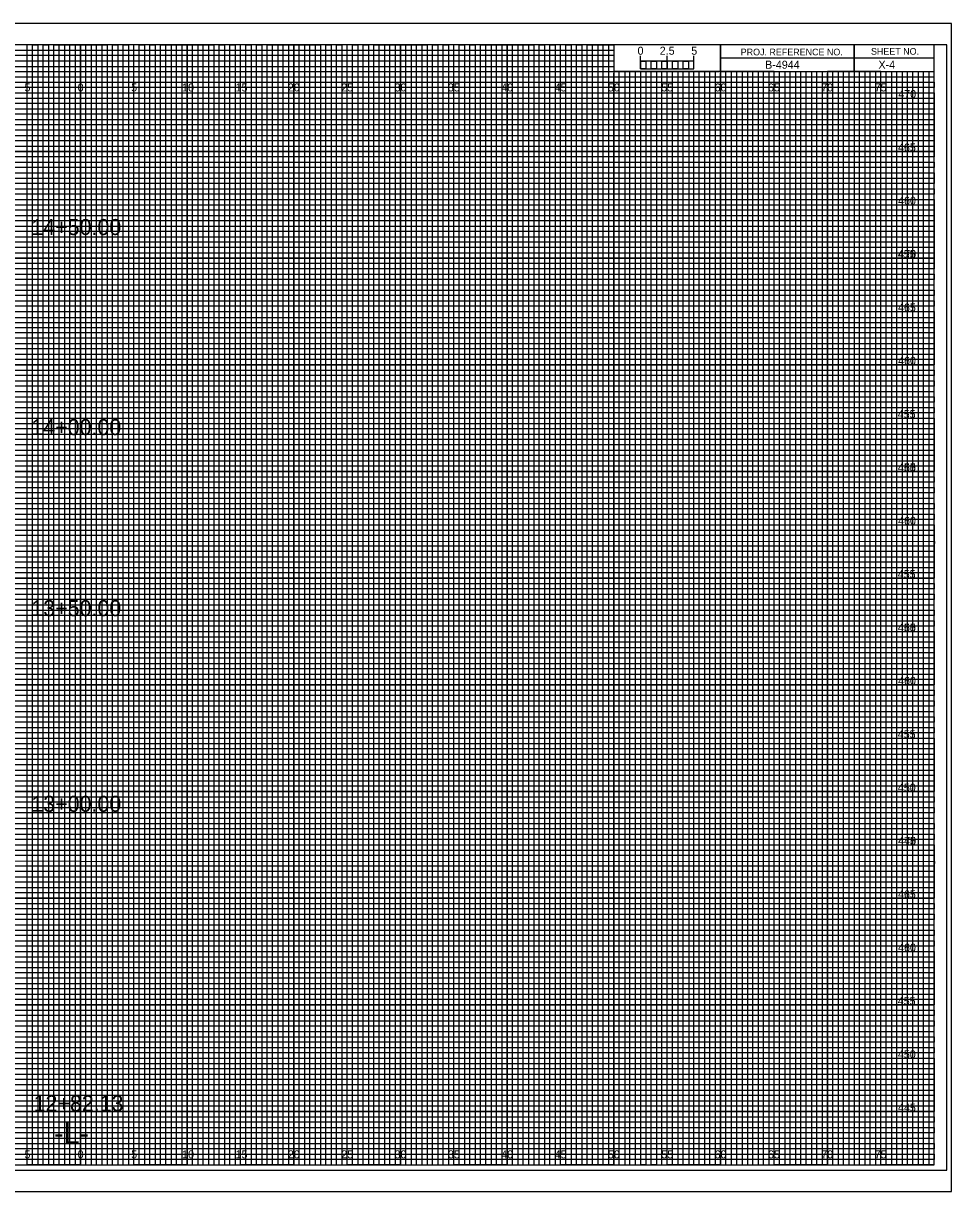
# Model space of a CAD drawing. Extents: x -7 to 162, y 328 to 437.
# Drawn here: x 74.6 to 161.7, y 327.5 to 437 of the extents above; entities that cross this region are included whole.
import ezdxf

# ---------------------------------------------------------------- set-up
doc = ezdxf.new("R2010")
doc.units = 0
for name, color, linetype in [('Prop XS Alignment Label', 7, 'Continuous'), ('Prop XS Bar Scale Labels', 7, 'Continuous'), ('Prop XS Elevation Labels', 7, 'Continuous'), ('Prop XS Offset Labels', 7, 'Continuous'), ('Prop XS Project Number', 7, 'Continuous'), ('Prop XS Sheet Number', 7, 'Continuous'), ('Prop XS Station Labels', 7, 'Continuous'), ('Sheet Cross Section CELL', 7, 'Continuous'), ('Sheet Cross Section Grid Major CELL', 7, 'Continuous'), ('Sheet Cross Section Grid Middle CELL', 7, 'Continuous'), ('Sheet Cross Section Grid Minor 1 CELL', 7, 'Continuous'), ('Sheet Cross Section Grid Minor 2 CELL', 7, 'Continuous'), ('Sheet Cross Section Scale CELL', 7, 'Continuous'), ('Sheet Cutting Line CELL', 7, 'Continuous'), ('Sheet DOT Grid CELL', 7, 'Continuous'), ('Sheet Plot Border Inside CELL', 7, 'Continuous'), ('Sheet Plot Border Outside CELL', 7, 'Continuous')]:
    doc.layers.add(name, color=color, linetype=linetype)

msp = doc.modelspace()

# ---------------------------------------------------------------- linework, layer by layer
at = {"layer": 'Sheet Cross Section CELL'}
for p, q in [((152.5, 435), (152.5, 432.5)), ((152.5, 432.5), (152.5, 435)), ((160, 433.75), (140, 433.75)), ((140, 433.75), (140, 432.5)), ((140, 432.5), (160, 432.5))]:
    msp.add_line(p, q, dxfattribs=at)
for points in [[(160, 435), (0, 435), (0, 330), (160, 330)], [(140, 435), (130, 435), (130, 432.51), (140, 432.51)], [(160, 435), (140, 435), (140, 432.5), (160, 432.5)]]:
    msp.add_lwpolyline(points, close=True, dxfattribs=at)
at = {"layer": 'Sheet Cross Section Grid Major CELL'}
for p, q in [((75, 435), (70, 435)), ((75, 330), (75, 435)), ((85, 435), (80, 435)), ((80, 435), (80, 330)), ((85, 330), (85, 435)), ((95, 435), (90, 435)), ((90, 435), (90, 330)), ((95, 330), (95, 435)), ((105, 435), (100, 435)), ((100, 435), (100, 330)), ((105, 330), (105, 435)), ((115, 435), (110, 435)), ((110, 435), (110, 330)), ((115, 330), (115, 435)), ((125, 435), (120, 435)), ((120, 435), (120, 330)), ((125, 330), (125, 435)), ((130, 435), (130, 330)), ((135, 330), (135, 432.5)), ((145, 432.5), (140, 432.5)), ((140, 432.5), (140, 330)), ((145, 330), (145, 432.5)), ((155, 432.5), (150, 432.5)), ((150, 432.5), (150, 330)), ((155, 330), (155, 432.5)), ((80, 330), (75, 330)), ((90, 330), (85, 330)), ((100, 330), (95, 330)), ((110, 330), (105, 330)), ((120, 330), (115, 330)), ((130, 330), (125, 330)), ((140, 330), (135, 330)), ((150, 330), (145, 330)), ((160, 330), (155, 330)), ((160, 330), (160, 330))]:
    msp.add_line(p, q, dxfattribs=at)
for points in [[(0, 430), (160, 430), (160, 425), (0, 425)], [(0, 420), (160, 420), (160, 415), (0, 415)], [(0, 410), (160, 410), (160, 405), (0, 405)], [(0, 400), (160, 400), (160, 395), (0, 395)], [(0, 390), (160, 390), (160, 385), (0, 385)], [(0, 380), (160, 380), (160, 375), (0, 375)], [(0, 370), (160, 370), (160, 365), (0, 365)], [(0, 360), (160, 360), (160, 355), (0, 355)], [(0, 350), (160, 350), (160, 345), (0, 345)], [(0, 340), (160, 340), (160, 335), (0, 335)]]:
    msp.add_lwpolyline(points, dxfattribs=at)
at = {"layer": 'Sheet Cross Section Grid Middle CELL'}
for points in [[(72.5, 330), (77.5, 330), (77.5, 435), (82.5, 435), (82.5, 330), (87.5, 330), (87.5, 435), (92.5, 435), (92.5, 330), (97.5, 330), (97.5, 435), (102.5, 435), (102.5, 330), (107.5, 330), (107.5, 435), (112.5, 435), (112.5, 330), (117.5, 330), (117.5, 435), (122.5, 435), (122.5, 330), (127.5, 330), (127.5, 435), (129.97, 435), (130, 435), (130, 432.5), (132.5, 432.5), (132.5, 330), (137.5, 330), (137.5, 432.5), (142.5, 432.5), (142.5, 330), (147.5, 330), (147.5, 432.5), (152.5, 432.5), (152.5, 330), (157.5, 330), (157.5, 432.5)], [(0, 432.5), (137.5, 432.5)], [(0, 422.5), (160, 422.5), (160, 427.5), (0, 427.5)], [(0, 412.5), (160, 412.5), (160, 417.5), (0, 417.5)], [(0, 402.5), (160, 402.5), (160, 407.5), (0, 407.5)], [(0, 392.5), (160, 392.5), (160, 397.5), (0, 397.5)], [(0, 382.5), (160, 382.5), (160, 387.5), (0, 387.5)], [(0, 372.5), (160, 372.5), (160, 377.5), (0, 377.5)], [(0, 362.5), (160, 362.5), (160, 367.5), (0, 367.5)], [(0, 352.5), (160, 352.5), (160, 357.5), (0, 357.5)], [(0, 342.5), (160, 342.5), (160, 347.5), (0, 347.5)], [(0, 332.5), (160, 332.5), (160, 337.5), (0, 337.5)]]:
    msp.add_lwpolyline(points, dxfattribs=at)
at = {"layer": 'Sheet Cross Section Grid Minor 1 CELL'}
for p, q in [((0, 434.5), (130, 434.5)), ((130, 433.99), (0, 433.99)), ((130, 434.5), (130, 433.99)), ((0, 433.5), (130, 433.5)), ((130, 432.94), (0, 432.94)), ((130, 433.5), (130, 432.94)), ((0, 432), (160, 432))]:
    msp.add_line(p, q, dxfattribs=at)
for points in [[(0, 431.5), (135, 431.5), (160, 431.5), (160, 431), (0, 431)], [(0, 430.5), (160, 430.5), (160, 429.5), (0, 429.5)], [(0, 429), (160, 429), (160, 428.5), (0, 428.49)], [(0, 428), (160, 428), (160, 427), (0, 427)], [(0, 426.5), (160, 426.5), (160, 426), (0, 426)], [(0, 425.5), (160, 425.5), (160, 424.5), (0, 424.5)], [(0, 424), (160, 424), (160, 423.5), (0, 423.5)], [(0, 423), (160, 423), (160, 422), (0, 422)], [(0, 421.5), (160, 421.5), (160, 421), (0, 421)], [(0, 420.5), (160, 420.5), (160, 419.5), (0, 419.5)], [(0, 419), (160, 419), (160, 418.5), (0, 418.5)], [(0, 418), (160, 418), (160, 416.98), (160, 416.5), (160, 416), (0, 416)], [(0, 417), (160, 417), (160, 416.5), (0, 416.5)], [(0, 415.5), (160, 415.5), (160, 414.5), (0, 414.51)], [(0, 414.51), (160, 414.5), (160, 414), (0, 414)], [(0, 413.5), (160, 413.5), (160, 413), (0, 413)], [(0, 412), (160, 412), (160, 411.5), (0, 411.5)], [(0, 411), (160, 411), (160, 410.5), (0, 410.5)], [(-0.04, 409.44), (160, 409.44), (160, 408.94), (-0.04, 408.94)], [(0, 408.5), (160, 408.5), (160, 408), (0, 408)], [(0, 407), (160, 407), (160, 406.5), (0, 406.5)], [(0, 406), (160, 406), (160, 405.5), (0, 405.5)], [(0, 404.5), (160, 404.5), (160, 404), (0, 404)], [(0, 403.5), (160, 403.5), (160, 403), (0, 403)], [(0, 402), (160, 402), (160, 401.5), (0, 401.5)], [(0, 401), (160, 401), (160, 400.5), (0, 400.5)], [(0, 399.5), (160, 399.5), (160, 398.99), (0, 399)], [(0, 398.5), (160, 398.5), (160, 398), (0, 398)], [(0, 397), (160, 397), (160, 396.5), (0, 396.5)], [(0, 396), (160, 396), (160, 395.5), (0, 395.5)], [(0, 394.5), (160, 394.5), (160, 394), (0, 394)], [(0, 393.5), (160, 393.5), (160, 393), (0, 393)], [(0, 392), (160, 392), (160, 391.5), (0, 391.5)], [(0, 391), (160, 391), (160, 390.5), (0, 390.5)], [(0, 389.5), (160, 389.5), (160, 389), (0, 389)], [(0, 388.5), (160.03, 388.45), (160, 388), (0, 388)], [(0, 387), (160, 387), (160, 386.5), (0, 386.5)], [(0, 386), (160, 386), (160, 385.5), (0, 385.5)], [(0, 384.5), (160, 384.5), (160, 384), (0, 384)], [(0, 383.5), (160, 383.5), (160, 383), (0, 383)], [(0, 382), (160, 382), (160, 381.5), (0, 381.5)], [(0, 381), (160, 381), (160, 380.5), (0, 380.5)], [(0, 379.5), (160, 379.5), (160, 379), (0, 379)], [(0, 378.5), (160, 378.5), (160, 378), (0, 378)], [(0, 377), (160, 377), (160, 376.5), (0, 376.5)], [(0, 376), (160, 376), (160, 375.5), (0, 375.5)], [(0, 374.5), (160, 374.5), (160, 374), (0, 374)], [(0, 373.5), (160, 373.5), (160, 373), (0, 373)], [(0, 372), (160, 372), (160, 371.5), (0, 371.5)], [(0, 371), (160, 371), (160, 370.5), (0, 370.5)], [(0, 369.5), (160, 369.5), (160, 368.99), (0, 369)], [(0, 368.5), (160, 368.5), (160, 368), (0, 368)], [(0, 367), (160, 367), (160, 366.5), (0, 366.5)], [(0, 366), (160, 366), (160, 365.5), (0, 365.5)], [(0, 364.5), (160, 364.5), (160, 364), (0, 364)], [(0, 363.5), (160, 363.5), (160, 363), (0, 363)], [(0, 362), (160, 362), (160, 361.5), (0, 361.5)], [(0, 361), (160, 361), (160, 360.5), (0, 360.5)], [(0, 359.5), (160, 359.5), (160, 359), (0, 359)], [(0, 358.5), (160.03, 358.45), (160, 358), (0, 358)], [(0, 357), (160, 357), (160, 356.5), (0, 356.5)], [(0, 356), (160, 356), (160, 355.5), (0, 355.5)], [(0, 354.5), (160, 354.5), (160, 354), (0, 354)], [(0, 353.5), (160, 353.5), (160, 353), (0, 353)], [(0, 352), (160, 352), (160, 351.5), (0, 351.5)], [(0, 351), (160, 351), (160, 350.5), (0, 350.5)], [(0, 349.5), (160, 349.5), (160, 349), (0, 349)], [(0, 348.5), (160, 348.5), (160, 348), (0, 348)], [(0, 347), (160, 347), (160, 346.5), (0, 346.5)], [(0, 346), (160, 346), (160, 345.5), (0, 345.5)], [(0, 344.5), (160, 344.5), (160, 344), (0, 344)], [(0, 343.5), (160, 343.5), (160, 343), (0, 343)], [(0, 342), (160, 342), (160, 341.5), (0, 341.5)], [(0, 341), (160, 341), (160, 340.5), (0, 340.5)], [(0, 339.5), (160, 339.5), (160, 339), (0, 339)], [(0, 338.5), (160, 338.5), (160, 338), (0, 338)], [(0, 337), (160, 337), (160, 336.5), (0, 336.5)], [(0, 336), (160, 336), (160, 335.5), (0, 335.5)], [(0, 334.5), (160, 334.5), (160, 334), (0, 334)], [(0, 333.5), (160, 333.5), (160, 333), (0, 333)], [(0, 332), (160, 332), (160, 331.5), (0, 331.5)], [(0, 331), (160, 331), (160, 330.5), (0, 330.5)]]:
    msp.add_lwpolyline(points, dxfattribs=at)
at = {"layer": 'Sheet Cross Section Grid Minor 2 CELL'}
for p, q in [((133.5, 432.5), (133, 432.5)), ((133, 432.5), (133, 330)), ((133.5, 330), (133.5, 432.5)), ((134.5, 432.5), (134, 432.5)), ((134, 432.5), (134, 330)), ((134.5, 330), (134.5, 432.5)), ((133, 330), (132.5, 330)), ((134, 330), (133.5, 330))]:
    msp.add_line(p, q, dxfattribs=at)
for points in [[(75, 330), (75.5, 330), (75.5, 435), (76, 435), (76, 330)], [(76, 330), (76.5, 330), (76.5, 435), (77, 435), (77, 330)], [(77.5, 330), (78, 330), (78, 435), (78.5, 435), (78.5, 330)], [(78.5, 330), (79, 330), (79, 435), (79.5, 435), (79.5, 330)], [(80, 330), (80.5, 330), (80.5, 435), (81, 435), (81, 330)], [(81, 330), (81.5, 330), (81.5, 435), (82, 435), (82, 330)], [(82.5, 330), (83, 330), (83, 435), (83.5, 435), (83.5, 330)], [(83.5, 330), (84, 330), (84, 435), (84.5, 435), (84.5, 330)], [(85, 330), (85.5, 330), (85.5, 435), (86, 435), (86, 330)], [(86, 330), (86.5, 330), (86.5, 435), (87, 435), (87, 330)], [(87.5, 330), (88, 330), (88, 435), (88.5, 435), (88.5, 330)], [(88.5, 330), (89, 330), (89, 435), (89.5, 435), (89.5, 330)], [(90, 330), (90.5, 330), (90.5, 435), (91, 435), (91, 330)], [(91, 330), (91.5, 330), (91.5, 435), (92, 435), (92, 330)], [(92.5, 330), (93, 330), (93, 435), (93.5, 435), (93.5, 330)], [(93.5, 330), (94, 330), (94, 435), (94.5, 435), (94.5, 330)], [(95, 330), (95.5, 330), (95.5, 435), (96, 435), (96, 330)], [(96, 330), (96.5, 330), (96.5, 435), (97, 435), (97, 330)], [(97.5, 330), (98, 330), (98, 435), (98.5, 435), (98.5, 330)], [(98.5, 330), (99, 330), (99, 435), (99.5, 435), (99.5, 330)], [(100, 330), (100.5, 330), (100.5, 435), (101, 435), (101, 330)], [(101, 330), (101.5, 330), (101.5, 435), (102, 435), (102, 330)], [(102.5, 330), (103, 330), (103, 435), (103.5, 435), (103.5, 330)], [(103.5, 330), (104, 330), (104, 435), (104.5, 435), (104.5, 330)], [(105, 330), (105.5, 330), (105.5, 435), (106, 435), (106, 330)], [(106, 330), (106.5, 330), (106.5, 435), (107, 435), (107, 330)], [(107.5, 330), (108, 330), (108, 435), (108.5, 435), (108.5, 330)], [(108.5, 330), (109, 330), (109, 435), (109.5, 435), (109.5, 330)], [(110, 330), (110.5, 330), (110.5, 435), (111, 435), (111, 330)], [(111, 330), (111.5, 330), (111.5, 435), (112, 435), (112, 330)], [(112.5, 330), (113, 330), (113, 435), (113.5, 435), (113.5, 330)], [(113.5, 330), (114, 330), (114, 435), (114.5, 435), (114.5, 330)], [(115, 330), (115.5, 330), (115.5, 435), (116, 435), (116, 330)], [(116, 330), (116.5, 330), (116.5, 435), (117, 435), (117, 330)], [(117.5, 330), (118, 330), (118, 435), (118.5, 435), (118.5, 330)], [(118.5, 330), (119, 330), (119, 435), (119.5, 435), (119.5, 330)], [(120, 330), (120.5, 330), (120.5, 435), (121, 435), (121, 330)], [(121, 330), (121.5, 330), (121.5, 435), (122, 435), (122, 330)], [(122.5, 330), (123, 330), (123, 435), (123.5, 435), (123.5, 330)], [(123.5, 330), (124, 330), (124, 435), (124.5, 435), (124.5, 330)], [(125, 330), (125.5, 330), (125.5, 435), (126, 435), (126, 330)], [(126, 330), (126.5, 330), (126.5, 435), (127, 435), (127, 330)], [(127.5, 330), (128, 330), (128, 435), (128.5, 435), (128.5, 330)], [(128.5, 330), (129, 330), (129, 435), (129.5, 435), (129.5, 330)], [(130, 330), (130.5, 330), (130.5, 432.5), (131.01, 432.5), (131.01, 330)], [(131, 330), (131.5, 330), (131.5, 432.5), (132, 432.5), (132, 330)], [(135, 330), (135.49, 330), (135.49, 432.5), (136, 432.5), (136, 330)], [(136, 330), (136.5, 330), (136.5, 432.5), (137.03, 432.5), (137.03, 330)], [(137.5, 330), (138, 330), (138, 432.5), (138.5, 432.5), (138.5, 330)], [(138.5, 330), (139, 330), (139, 432.5), (139.5, 432.5), (139.5, 330)], [(140, 330), (140.5, 330), (140.5, 432.5), (141, 432.5), (141, 330)], [(141, 330), (141.5, 330), (141.5, 432.5), (142, 432.5), (142, 330)], [(142.5, 330), (143, 330), (143, 432.5), (143.5, 432.5), (143.5, 330)], [(143.5, 330), (144, 330), (144, 432.5), (144.5, 432.5), (144.5, 330)], [(145, 330), (145.5, 330), (145.5, 432.5), (146, 432.5), (146, 330)], [(146, 330), (146.5, 330), (146.5, 432.5), (147, 432.5), (147, 330)], [(147.5, 330), (148, 330), (148, 432.5), (148.5, 432.5), (148.5, 330)], [(148.5, 330), (149, 330), (149, 432.5), (149.5, 432.5), (149.5, 330)], [(150, 330), (150.5, 330), (150.5, 432.5), (151, 432.5), (151, 330)], [(151, 330), (151.5, 330), (151.5, 432.5), (152, 432.5), (152, 330)], [(152.5, 330), (153, 330), (153, 432.5), (153.5, 432.5), (153.5, 330)], [(153.5, 330), (154, 330), (154, 432.5), (154.5, 432.5), (154.5, 330)], [(155, 330), (155.5, 330), (155.5, 432.5), (156, 432.5), (156, 330)], [(156, 330), (156.5, 330), (156.5, 432.5), (157, 432.5), (157, 330)], [(157.5, 330), (158, 330), (158, 432.5), (158.5, 432.5), (158.5, 330)], [(158.5, 330), (159, 330), (159, 432.5), (159.5, 432.5), (159.5, 330)]]:
    msp.add_lwpolyline(points, dxfattribs=at)
at = {"layer": 'Sheet Cross Section Scale CELL'}
for p, q in [((132.5, 432.75), (132.5, 433.95)), ((132.5, 433.45), (132.5, 433.95)), ((135, 432.75), (135, 433.95)), ((137.5, 432.75), (137.5, 433.95)), ((137.5, 433.45), (137.5, 433.95))]:
    msp.add_line(p, q, dxfattribs=at)
for points in [[(137.5, 433.45), (132.5, 433.45), (132.5, 432.75), (137.5, 432.75)], [(132.5, 433.45), (133, 433.45), (133, 432.75), (132.5, 432.75)], [(133.5, 433.45), (134, 433.45), (134, 432.75), (133.5, 432.75)], [(134.5, 433.45), (135, 433.45), (135, 432.75), (134.5, 432.75)], [(135.5, 433.45), (136, 433.45), (136, 432.75), (135.5, 432.75)], [(136.5, 433.45), (137, 433.45), (137, 432.75), (136.5, 432.75)]]:
    msp.add_lwpolyline(points, close=True, dxfattribs=at)
at = {"layer": 'Sheet Cutting Line CELL'}
for p, q in [((161.65, 437), (-6.7, 437)), ((-6.7, 327.5), (161.65, 327.5))]:
    msp.add_line(p, q, dxfattribs=at)
at = {"layer": 'Sheet DOT Grid CELL'}
for p, q in [((75, 330), (75, 435)), ((80, 330), (80, 435)), ((85, 330), (85, 435)), ((90, 330), (90, 435)), ((95, 330), (95, 435)), ((100, 330), (100, 435)), ((105, 330), (105, 435)), ((110, 330), (110, 435)), ((115, 330), (115, 435)), ((120, 330), (120, 435)), ((125, 330), (125, 435)), ((130, 330), (130, 432.34)), ((135, 330), (135, 432.34)), ((140, 330), (140, 432.34)), ((145, 330), (145, 432.34)), ((150, 330), (150, 432.34)), ((155, 330), (155, 432.34)), ((0, 430), (160, 430)), ((0, 425), (160, 425)), ((0, 420), (160, 420)), ((0, 415), (160, 415)), ((0, 410), (160, 410)), ((0, 405), (160, 405)), ((0, 400), (160, 400)), ((0, 395), (160, 395)), ((0, 390), (160, 390)), ((0, 385), (160, 385)), ((0, 380), (160, 380)), ((0, 375), (160, 375)), ((0, 370), (160, 370)), ((0, 365), (160, 365)), ((0, 360), (160, 360)), ((0, 355), (160, 355)), ((0, 350), (160, 350)), ((0, 345), (160, 345)), ((0, 340), (160, 340)), ((0, 335), (160, 335))]:
    msp.add_line(p, q, dxfattribs=at)
at = {"layer": 'Sheet Plot Border Inside CELL'}
msp.add_lwpolyline([(-5.4, 329.5), (161.2, 329.5), (161.2, 435), (-5.4, 435)], close=True, dxfattribs=at)
at = {"layer": 'Sheet Plot Border Outside CELL'}
msp.add_lwpolyline([(-6.7, 327.5), (161.65, 327.5), (161.65, 437), (-6.7, 437)], close=True, dxfattribs=at)

# ---------------------------------------------------------------- texts
at = {"layer": 'Prop XS Alignment Label'}
msp.add_text('-L-', height=2, dxfattribs=at).set_placement((77.53, 332))
at = {"layer": 'Prop XS Bar Scale Labels'}
for s, p in [('2.5', (134.29, 434.06)), ('5', (137.24, 434.06))]:
    msp.add_text(s, height=0.75, dxfattribs=at).set_placement(p)
at = {"layer": 'Prop XS Elevation Labels'}
for s, p in [('470', (156.65, 430)), ('465', (156.62, 425)), ('460', (156.63, 420)), ('455', (156.6, 415)), ('470', (156.65, 415)), ('465', (156.62, 410)), ('460', (156.63, 405)), ('455', (156.6, 400)), ('450', (156.61, 395)), ('465', (156.62, 395)), ('460', (156.63, 390)), ('455', (156.6, 385)), ('450', (156.61, 380)), ('465', (156.62, 380)), ('460', (156.63, 375)), ('455', (156.6, 370)), ('450', (156.61, 365)), ('445', (156.62, 360)), ('470', (156.65, 360)), ('465', (156.62, 355)), ('460', (156.63, 350)), ('455', (156.6, 345)), ('450', (156.61, 340)), ('445', (156.62, 335))]:
    msp.add_text(s, height=0.75, dxfattribs=at).set_placement(p)
at = {"layer": 'Prop XS Offset Labels'}
for s, p in [('5', (74.74, 430.62)), ('0', (79.73, 430.62)), ('0', (79.73, 430.62)), ('5', (84.74, 430.62)), ('10', (89.52, 430.62)), ('15', (94.53, 430.62)), ('20', (99.43, 430.62)), ('25', (104.44, 430.62)), ('30', (109.43, 430.62)), ('35', (114.44, 430.62)), ('40', (119.43, 430.62)), ('45', (124.44, 430.62)), ('50', (129.43, 430.62)), ('55', (134.44, 430.62)), ('60', (139.43, 430.62)), ('65', (144.44, 430.62)), ('70', (149.43, 430.62)), ('75', (154.44, 430.62)), ('5', (74.74, 330.62)), ('0', (79.73, 330.62)), ('0', (79.73, 330.62)), ('5', (84.74, 330.62)), ('10', (89.52, 330.62)), ('15', (94.53, 330.62)), ('20', (99.43, 330.62)), ('25', (104.44, 330.62)), ('30', (109.43, 330.62)), ('35', (114.44, 330.62)), ('40', (119.43, 330.62)), ('45', (124.44, 330.62)), ('50', (129.43, 330.62)), ('55', (134.44, 330.62)), ('60', (139.43, 330.62)), ('65', (144.44, 330.62)), ('70', (149.43, 330.62)), ('75', (154.44, 330.62))]:
    msp.add_text(s, height=0.75, dxfattribs=at).set_placement(p)
at = {"layer": 'Prop XS Project Number'}
msp.add_text('B-4944', height=0.75, dxfattribs=at).set_placement((144.17, 432.75))
at = {"layer": 'Prop XS Sheet Number'}
msp.add_text('X-4', height=0.75, dxfattribs=at).set_placement((154.79, 432.75))
at = {"layer": 'Prop XS Station Labels'}
for s, p in [('14+50.00', (75.39, 417.16)), ('14+00.00', (75.39, 398.41)), ('13+50.00', (75.39, 381.44)), ('13+00.00', (75.39, 363.1)), ('12+82.13', (75.6, 335.03))]:
    msp.add_text(s, height=1.5, dxfattribs=at).set_placement(p)
at = {"layer": 'Sheet Cross Section CELL'}
for s, p in [('PROJ. REFERENCE NO.', (141.88, 434)), ('SHEET NO.', (154.09, 434.06))]:
    msp.add_text(s, height=0.625, dxfattribs=at).set_placement(p)
at = {"layer": 'Sheet Cross Section Scale CELL'}
msp.add_text('0', height=0.75, dxfattribs=at).set_placement((132.21, 434.06))

doc.saveas('drawing.dxf')
